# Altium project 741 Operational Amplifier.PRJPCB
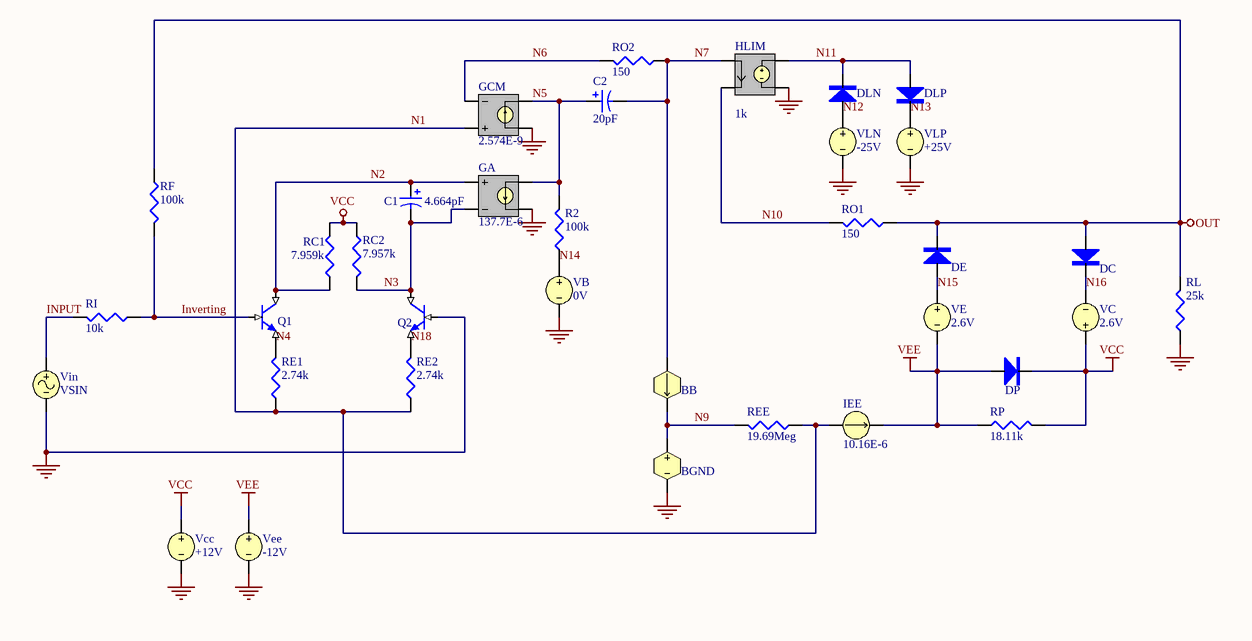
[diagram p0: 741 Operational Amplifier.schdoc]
1 sheet, 35 parts. Net scope: global (net labels, ports and power ports of the same name join across sheets).

## Sheet 741 Operational Amplifier.schdoc: 741 Operational Amplifier Simulation
size A4; Organization: Altium Limited; Address1: L3, 12a Rodborough Rd; Address2: Frenchs Forest; Address3: NSW; Address4: Australia 2086; DocumentNumber: 1; SheetNumber: 1; SheetTotal: 1

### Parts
BB  I(VB)*10.61E6-I(VC)*10E6+I(VE)*10E6+I(VLP)*10E6-I(VLN)*10E6  (value not drawn)
BGND  V(VCC)*.5+V(VEE)*.5  (value not drawn)
C1  4.664pF
C2  20pF
DC  1N914  (value not drawn)
DE  1N914  (value not drawn)
DLN  1N914  (value not drawn)
DLP  1N914  (value not drawn)
DP  1N914  (value not drawn)
GA  137.7E-6
GCM  2.574E-9
HLIM  1k
IEE  10.16E-6
Q1  2N2222A  (value not drawn)
Q2  2N2222A  (value not drawn)
R2  100k
RC1  7.959k
RC2  7.957k
RE1  2.74k
RE2  2.74k
REE  19.69Meg
RF  100k
RI  10k
RL  25k
RO1  150
RO2  150
RP  18.11k
VB  0V
VC  2.6V
Vcc  +12V
VE  2.6V
Vee  -12V
Vin  VSIN
VLN  -25V
VLP  +25V

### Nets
GND: BGND.2 GA.4(N-) GCM.3(N+) HLIM.4(N-) Q2.2(B) RL.2(BOT) VB.2 Vcc.2 Vee.2 Vin.2 VLN.2 VLP.2
OUT: DC.1(A) DE.2(K) RF.2(BOT) RL.1(TOP) RO1.2(BOT)
VCC: DP.2(K) RC1.1(TOP) RC2.2(BOT) RP.1(TOP) VC.1 Vcc.1
VEE: DP.1(A) IEE.2 RP.2(BOT) VE.2 Vee.1
INPUT: RI.1(TOP) Vin.1
Inverting: Q1.2(B) RF.1(TOP) RI.2(BOT)
N1: GCM.1(NC+) IEE.1 RE1.2(BOT) RE2.2(BOT) REE.2(BOT)
N2: C1.1 GA.1(NC+) Q1.1(C) RC1.2(BOT)
N3: C1.2 GA.2(NC-) Q2.1(C) RC2.1(TOP)
N4: Q1.3(E) RE1.1(TOP)
N5: C2.1 GA.3(N+) GCM.4(N-) R2.1(TOP)
N6: GCM.2(NC-) RO2.1(TOP)
N7: BB.1 C2.2 HLIM.1(NC+) RO2.2(BOT)
N9: BB.2 BGND.1 REE.1(TOP)
N10: HLIM.2(NC-) RO1.1(TOP)
N11: DLN.2(K) DLP.1(A) HLIM.3(N+)
N12: DLN.1(A) VLN.1
N13: DLP.2(K) VLP.1
N14: R2.2(BOT) VB.1
N15: DE.1(A) VE.1
N16: DC.2(K) VC.2
N18: Q2.3(E) RE2.1(TOP)

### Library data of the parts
BB = BISRC: Non-Linear Dependent Current Source
BGND = BVSRC: Non-Linear Dependent Voltage Source
C1 C2 = CAP2: Bi-Polar Capacitor
DC DE DLN DLP DP = 1N914: Diode
GA GCM = GSRC: Voltage Controlled Current Source
HLIM = HSRC: Current Controlled Voltage Source
IEE = ISRC: Current Source
Q1 Q2 = 2N2222A: NPN BJT
R2 RC1 RC2 RE1 RE2 REE RF RI RL RO1 RO2 RP = RES: Resistor
VB VC Vcc VE Vee VLN VLP = VSRC: Voltage Source
Vin = VSIN: Sinusoidal Voltage Source; Offset: 0; Amplitude: 1; Frequency: 10k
